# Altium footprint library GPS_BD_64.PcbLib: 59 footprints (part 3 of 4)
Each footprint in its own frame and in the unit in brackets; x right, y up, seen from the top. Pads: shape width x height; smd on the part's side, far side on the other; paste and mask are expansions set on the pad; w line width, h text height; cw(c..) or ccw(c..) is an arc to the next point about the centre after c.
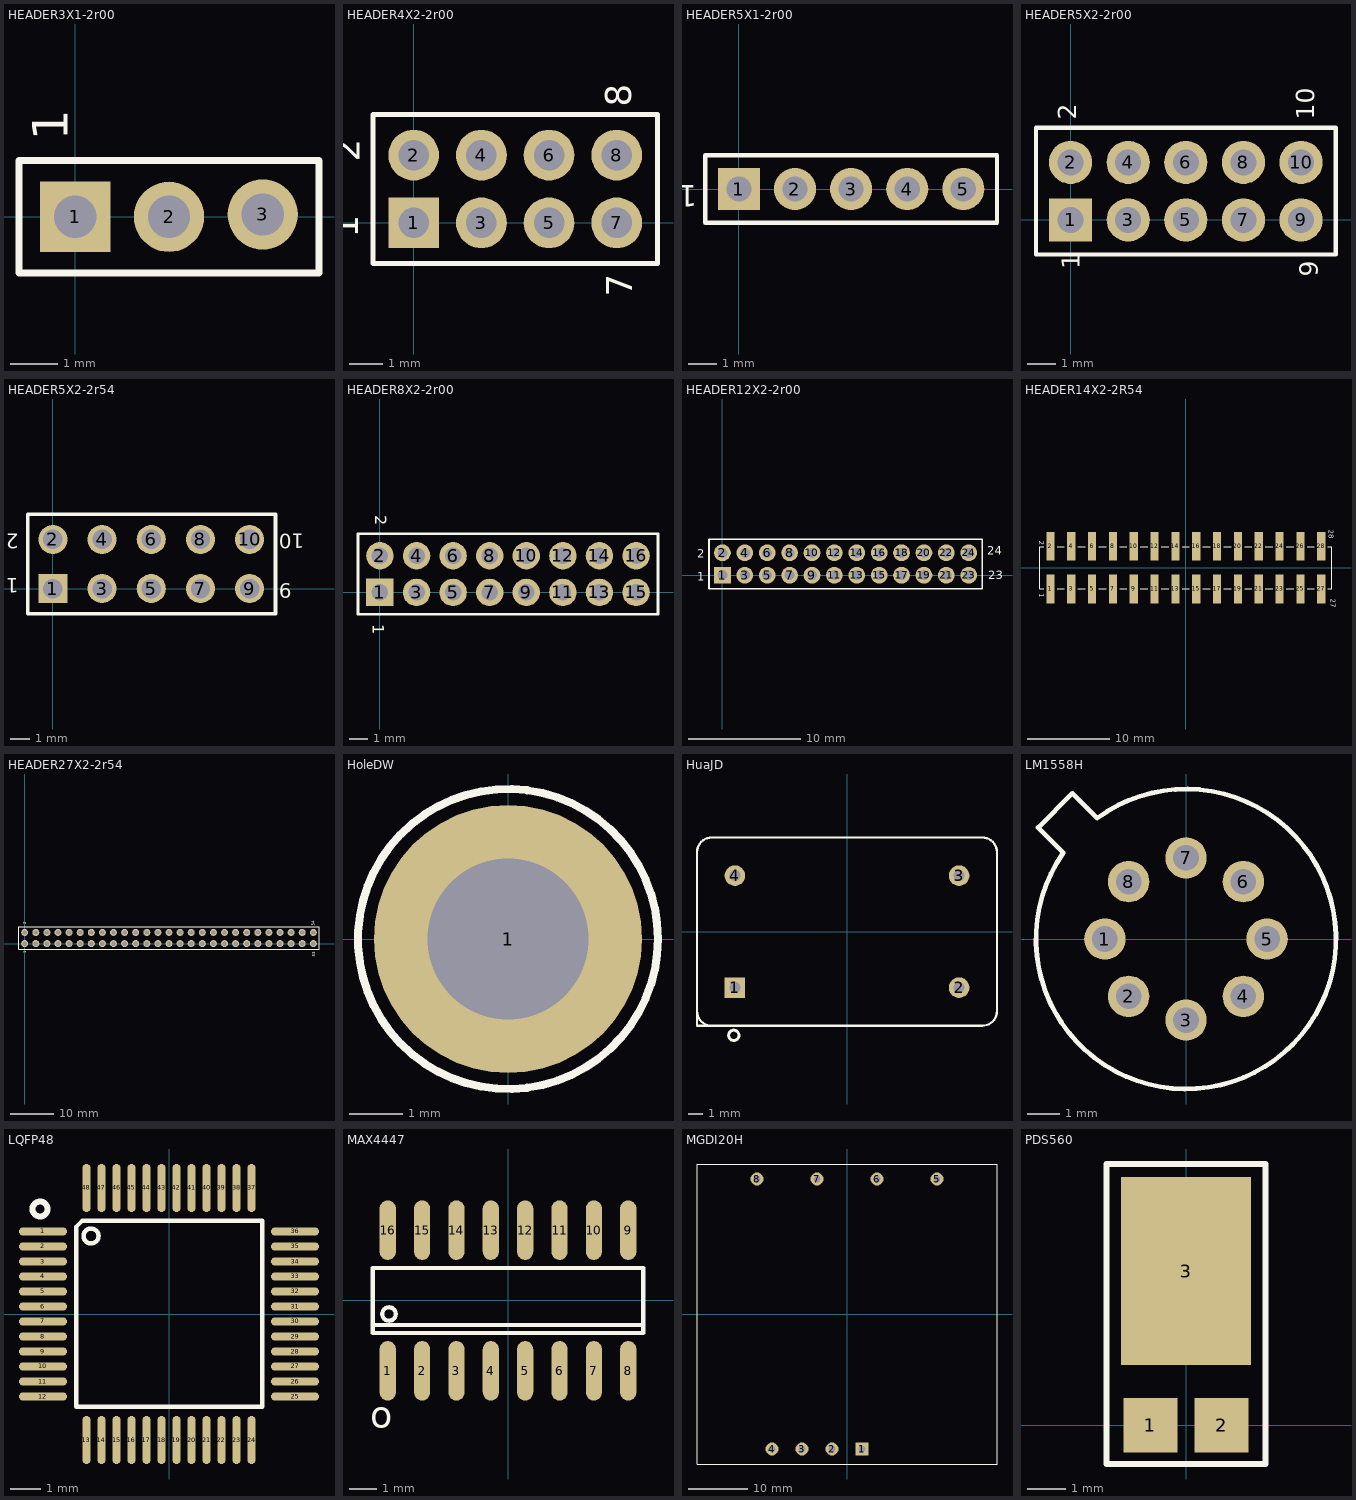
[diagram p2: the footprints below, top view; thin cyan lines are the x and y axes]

## HEADER3X1-2r00 [mm]
height 1.45
pads (3):
  rect 1.5x1.5 hole 0.9: 1(0,0)
  round 1.5 hole 0.9: 2(2,0) 3(4,0.05)
Top Overlay:
  lines w0.15: -1.2,-1.2 -1.2,1.2 5.2,1.2 5.2,-1.2 -1.2,-1.2
  text "1" at -0.158,1.624 h0.76

## HEADER4X2-2r00 [mm]
height 1.45
pads (8):
  rect 1.5x1.5 hole 0.9: 1(0,0)
  round 1.5 hole 0.9: 2(0,2) 3(2,0) 4(2,2) 5(4,0) 6(4,2) 7(6,0) 8(6,2)
Top Overlay:
  lines w0.15: -1.2,-1.2 -1.2,3.2 7.2,3.2 7.2,-1.2 -1.2,-1.2
  text "7" at 6.457,-2.191 h0.76
  text "8" at 6.435,3.428 h0.76
  text "2" at -1.591,1.803 h0.76
  text "1" at -1.647,-0.44 h0.76

## HEADER5X1-2r00 [mm]
height 1.45
pads (5):
  rect 1.5x1.5 hole 0.9: 1(0,0)
  round 1.5 hole 0.9: 2(2,0) 3(4,0) 4(6,0) 5(8,0)
Top Overlay:
  lines w0.15: -1.2,-1.2 9.2,-1.2 9.2,1.2 -1.2,1.2 -1.2,-1.2
  text "1" at -1.493,0.127 h0.76

## HEADER5X2-2r00 [mm]
pads (10):
  rect 1.5x1.5 hole 0.9: 1(0,0)
  round 1.5 hole 0.9: 2(0,2) 3(2,0) 4(2,2) 5(4,0) 6(4,2) 7(6,0) 8(6,2) 9(8,0) 10(8,2)
Top Overlay:
  lines w0.15: -1.2,-1.2 -1.2,3.2 9.2,3.2 9.2,-1.2 -1.2,-1.2
  text "9" at 8.579,-1.964 h0.64
  text "10" at 8.457,3.48 h0.64
  text "2" at 0.202,3.473 h0.64
  text "1" at 0.324,-1.71 h0.64

## HEADER5X2-2r54 [mm]
height 11
pads (10):
  rect 1.5x1.5 hole 1: 1(0,0)
  round 1.5 hole 1: 2(0,2.54) 3(2.54,0) 4(2.54,2.54) 5(5.08,0) 6(5.08,2.54) 7(7.62,0) 8(7.62,2.54) 9(10.16,0) 10(10.16,2.54)
Top Overlay:
  lines w0.2: -1.3,-1.3 -1.3,3.84 11.5,3.84 11.5,-1.3 -1.3,-1.3
  text "1" at -1.751,0.534 h0.76
  text "2" at -1.751,2.82 h0.76
  text "9" at 12.346,0.28 h0.76
  text "10" at 12.981,2.82 h0.76

## HEADER8X2-2r00 [mm]
height 1.45
pads (16):
  rect 1.5x1.5 hole 0.9: 1(0,0)
  round 1.5 hole 0.9: 2(0,2) 3(2,0) 4(2,2) 5(4,0) 6(4,2) 7(6,0) 8(6,2) 9(8,0) 10(8,2) 11(10,0) 12(10,2) 13(12,0) 14(12,2) 15(14,0) 16(14,2)
Top Overlay:
  lines w0.15: -1.2,-1.2 15.2,-1.2 15.2,3.2 -1.2,3.2 -1.2,-1.2
  text "2" at -0.256,4.218 h0.64
  text "1" at -0.383,-1.751 h0.64

## HEADER12X2-2r00 [mm]
height 1.45
pads (24):
  rect 1.5x1.5 hole 0.9: 1(0,0)
  round 1.5 hole 0.9: 2(0,2) 3(2,0) 4(2,2) 5(4,0) 6(4,2) 7(6,0) 8(6,2) 9(8,0) 10(8,2) 11(10,0) 12(10,2) 13(12,0) 14(12,2) 15(14,0) 16(14,2) 17(16,0) 18(16,2) 19(18,0) 20(18,2) 21(20,0) 22(20,2) 23(22,0) 24(22,2)
Top Overlay:
  lines w0.15: -1.2,-1.2 -1.2,3.2 23.2,3.2 23.2,-1.2 -1.2,-1.2
  text "24" at 23.637,1.809 h0.76
  text "23" at 23.764,-0.35 h0.76
  text "2" at -2.271,1.555 h0.76
  text "1" at -2.271,-0.477 h0.76

## HEADER14X2-2R54 [mm]
pads (28):
  rect 1x3.5 smd: 1(-16.51,-2.6) 2(-16.51,2.6) 3(-13.97,-2.6) 4(-13.97,2.6) 5(-11.43,-2.6) 6(-11.43,2.6) 7(-8.89,-2.6) 8(-8.89,2.6) 9(-6.35,-2.6) 10(-6.35,2.6) 11(-3.81,-2.6) 12(-3.81,2.6) 13(-1.27,-2.6) 14(-1.27,2.6) 15(1.27,-2.6) 16(1.27,2.6) 17(3.81,-2.6) 18(3.81,2.6) 19(6.35,-2.6) 20(6.35,2.6) 21(8.89,-2.6) 22(8.89,2.6) 23(11.43,-2.6) 24(11.43,2.6) 25(13.97,-2.6) 26(13.97,2.6) 27(16.51,-2.6) 28(16.51,2.6)
Top Overlay:
  lines w0.15: -17.3,-2.55 -17.81,-2.55 -17.81,2.55 -17.3,2.55 ; -15.7,-2.55 -14.8,-2.55 ; -15.7,2.55 -14.8,2.55 ; -13.16,-2.55 -12.26,-2.55 ; -13.16,2.55 -12.26,2.55 ; -10.62,-2.55 -9.72,-2.55 ; -10.62,2.55 -9.72,2.55 ; -8.08,-2.55 -7.18,-2.55 ; -8.08,2.55 -7.18,2.55 ; -5.54,-2.55 -4.64,-2.55 ; -5.54,2.55 -4.64,2.55 ; -3,-2.55 -2.1,-2.55 ; -3,2.55 -2.1,2.55 ; -0.46,-2.55 0.44,-2.55 ; -0.46,2.55 0.44,2.55 ; 2.08,-2.55 2.98,-2.55 ; 2.08,2.55 2.98,2.55 ; 4.62,-2.55 5.52,-2.55 ; 4.62,2.55 5.52,2.55 ; 7.16,-2.55 8.06,-2.55 ; 7.16,2.55 8.06,2.55 ; 9.7,-2.55 10.6,-2.55 ; 9.7,2.55 10.6,2.55 ; 12.24,-2.55 13.14,-2.55 ; 12.24,2.55 13.14,2.55 ; 14.78,-2.55 15.68,-2.55 ; 14.78,2.55 15.68,2.55 ; 17.3,-2.55 17.81,-2.55 17.81,2.55 17.3,2.55
  text "1" at -17.841,-3.106 h0.64
  text "2" at -17.849,3.29 h0.64
  text "28" at 17.417,4.595 h0.64
  text "27" at 17.668,-3.789 h0.64

## HEADER27X2-2r54 [mm]
height 1.45
pads (54):
  round 1.6 hole 1: 1(0,0) 2(0,2.54) 3(2.54,0) 4(2.54,2.54) 5(5.08,0) 6(5.08,2.54) 7(7.62,0) 8(7.62,2.54) 9(10.16,0) 10(10.16,2.54) 11(12.7,0) 12(12.7,2.54) 13(15.24,0) 14(15.24,2.54) 15(17.78,0) 16(17.78,2.54) 17(20.32,0) 18(20.32,2.54) 19(22.86,0) 20(22.86,2.54) 21(25.4,0) 22(25.4,2.54) 23(27.94,0) 24(27.94,2.54) 25(30.48,0) 26(30.48,2.54) 27(33.02,0) 28(33.02,2.54) 29(35.56,0) 30(35.56,2.54) 31(38.1,0) 32(38.1,2.54) 33(40.64,0) 34(40.64,2.54) 35(43.18,0) 36(43.18,2.54) 37(45.72,0) 38(45.72,2.54) 39(48.26,0) 40(48.26,2.54) 41(50.8,0) 42(50.8,2.54) 43(53.34,0) 44(53.34,2.54) 45(55.88,0) 46(55.88,2.54) 47(58.42,0) 48(58.42,2.54) 49(60.96,0) 50(60.96,2.54) 51(63.5,0) 52(63.5,2.54) 53(66.04,0) 54(66.04,2.54)
Top Overlay:
  lines w0.15: -1.3,-1.3 -1.3,3.84 67.34,3.84 67.34,-1.3 -1.3,-1.3
  text "1" at 0.344,-2.178 h0.64
  text "2" at 0.344,4.426 h0.64
  text "54" at 66.39,4.04 h0.64
  text "53" at 66.44,-2.96 h0.64

## HoleDW [mm]
height 1.45
pads (1):
  round 5 hole 3: 1(0,0)
Top Overlay:
  circle w0.15: c0,0 r2.8

## HuaJD [mm]
height 1.45
pads (4):
  rect 1.4x1.4 hole 0.75: 1(-7.62,-3.81)
  round 1.4 hole 0.75: 2(7.62,-3.81) 3(7.62,3.81) 4(-7.62,3.81)
Top Overlay:
  circle w0.2: c-7.7,-7.05 r0.35
  lines w0.15: -10.2,-5.4 ccw(c-9.2,-5.4) -9.2,-6.4 ; 9.2,6.4 cw(c9.2,5.4) 10.2,5.4 ; 9.25,6.4 -9.2,6.4 ccw(c-9.2,5.4) -10.2,5.4 -10.2,-6.4 9.2,-6.4 ccw(c9.2,-5.4) 10.2,-5.4 10.2,5.45

## LM1558H [mm]
height 11
pads (8):
  round 1.3 hole 0.8: 1(-2.54,0) 2(-1.796,-1.796) 3(0,-2.54) 4(1.796,-1.796) 5(2.54,0) 6(1.796,1.796) 7(0,2.54) 8(-1.796,1.796)
Top Overlay:
  lines w0.15: -3.849,2.706 -4.635,3.492 -3.559,4.569 -2.779,3.79 cw(c0,0) -3.845,2.703

## LQFP48 [mm]
height 11
pads (48):
  oval 1.6x0.28 smd: 1(-4.2,2.75) 2(-4.2,2.25) 3(-4.2,1.75) 4(-4.2,1.25) 5(-4.2,0.75) 6(-4.2,0.25) 7(-4.2,-0.25) 8(-4.2,-0.75) 9(-4.2,-1.25) 10(-4.2,-1.75) 11(-4.2,-2.25) 12(-4.2,-2.75) 25(4.2,-2.75) 26(4.2,-2.25) 27(4.2,-1.75) 28(4.2,-1.25) 29(4.2,-0.75) 30(4.2,-0.25) 31(4.2,0.25) 32(4.2,0.75) 33(4.2,1.25) 34(4.2,1.75) 35(4.2,2.25) 36(4.2,2.75)
  oval 0.28x1.6 smd: 13(-2.75,-4.2) 14(-2.25,-4.2) 15(-1.75,-4.2) 16(-1.25,-4.2) 17(-0.75,-4.2) 18(-0.25,-4.2) 19(0.25,-4.2) 20(0.75,-4.2) 21(1.25,-4.2) 22(1.75,-4.2) 23(2.25,-4.2) 24(2.75,-4.2) 37(2.75,4.2) 38(2.25,4.2) 39(1.75,4.2) 40(1.25,4.2) 41(0.75,4.2) 42(0.25,4.2) 43(-0.25,4.2) 44(-0.75,4.2) 45(-1.25,4.2) 46(-1.75,4.2) 47(-2.25,4.2) 48(-2.75,4.2)
Top Overlay:
  circle w0.2: c-4.3,3.5 r0.25
  circle w0.15: c-2.6,2.6 r0.25
  lines w0.15: -3.1,-3.1 3.1,-3.1 3.1,3.1 -2.9,3.1 -3.1,2.9 -3.1,-3.1

## MAX4447 [mm] "MAX4447"
height 7
pads (16):
  oval 0.6x2.2 smd: 1(-4.445,-2.6) 2(-3.175,-2.6) 3(-1.905,-2.6) 4(-0.635,-2.6) 5(0.635,-2.6) 6(1.905,-2.6) 7(3.175,-2.6) 8(4.445,-2.6) 9(4.445,2.6) 10(3.175,2.6) 11(1.905,2.6) 12(0.635,2.6) 13(-0.635,2.6) 14(-1.905,2.6) 15(-3.175,2.6) 16(-4.445,2.6)
Top Overlay:
  circle w0.15: c-4.4,-0.5 r0.25
  lines w0.15: -5,-0.9 5,-0.9 ; -5,-1.2 -5,1.2 5,1.2 5,-1.2 -5,-1.2
  text "o" at -5.1,-4.7 h0.98

## MGDI20H [mm]
height 1.45
pads (8):
  rect 2.2x2.2 hole 1.2: 1(2.54,-22.86)
  round 2.2 hole 1.2: 2(-2.54,-22.86) 3(-7.62,-22.86) 4(-12.7,-22.86) 5(15.24,22.86) 6(5.08,22.86) 7(-5.08,22.86) 8(-15.24,22.86)
Top Overlay:
  lines w0.15: -25.4,-25.4 -25.4,25.4 25.4,25.4 25.4,-25.4 -25.4,-25.4

## PDS560 [mm]
height 1.45
pads (3):
  rect 1.4x1.4 smd: 1(-0.92,0) 2(0.92,0)
  rect 3.36x4.86 smd: 3(0,3.982)
Top Overlay:
  lines w0.15: -2.05,-1 -2.05,6.75 2.05,6.75 2.05,-1 -2.05,-1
